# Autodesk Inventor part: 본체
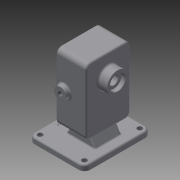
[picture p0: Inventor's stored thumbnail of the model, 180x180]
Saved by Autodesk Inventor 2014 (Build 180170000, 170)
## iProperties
Created: 2020-04
Part Number: 본체
Material: Generic
Document SubType Name: Modeling
Designer: kh
Density: 1 g/cm^3
Appearance: Default
Author: kh
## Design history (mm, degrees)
sketch "스케치1"
  geometry: L1 (-50, 60)-(50, 60); L2 (50, 60)-(50, -60); L3 (50, -60)-(-50, -60); L4 (-50, -60)-(-50, 60); L5 (-50, 60)-(50, -60); L6 (50, 60)-(-50, -60); 1 further point
  constraints: 12 end point, 2 midpoint, 2 parallel, 1 horizontal, 1 perpendicular
  dimensions: "d0" = 100 distance of L1.start L1.end; "d1" = 120 distance of L3.end L1.start
extrude "돌출1" new body sketch "스케치1" distance "d2" = 10; taper "d3" = 0 deg
fillet "모깎기1" dims "d7" = 10
sketch "스케치4"
  geometry: A1 r 10 centre (-40, 50) between (-40, 60) and (-50, 50) reference; A2 r 10 centre (40, 50) between (50, 50) and (40, 60) reference; A3 r 10 centre (40, -50) between (40, -60) and (50, -50) reference; A4 r 10 centre (-40, -50) between (-50, -50) and (-40, -60) reference; 1 further point
hole "구멍2" sketch "스케치4" at (-40, -50), (40, -50), (40, 50), (-40, 50) diameter "d17" = 9; stored, may be unused: countersink angle "d21" = 90 deg, drill point angle "d23" = 118 deg; dims "d18" = 6, "d19" = 4, "d20" = 2, "d22" = 8
fillet "모깎기2" dims "d24" = 3
sketch "스케치5"
  geometry: L1 (-33, 150)-(20, 150); L2 (20, 150)-(20, 30); L3 (20, 30)-(-33, 30); L4 (-33, 30)-(-33, 150); L5 (50, 0)-(40, 0) reference; L6 (50, 0)-(50, 7) reference; L7 (-50, 7)-(-50, 0) reference; 2 further points
  constraints: 8 end point, 2 parallel, 1 horizontal, 1 midpoint, 1 perpendicular, 1 vertical alignment
  dimensions: "d25" = 53 distance of L1.start L1.end; "d26" = 120 distance of L3.end L1.start; "d27" = 150 distance between parallel lines of L5 L1; "d114" = 70 distance between parallel lines of L7 L2
extrude "돌출2" join sketch "스케치5" stored distance "d28" = 80; taper "d29" = 0 deg
fillet "모깎기3" dims "d31" = 9
sketch "스케치8"
  geometry: A1 r 9 centre (9, 62) between (9, 71) and (0, 62) reference; A2 r 9 centre (111, 62) between (120, 62) and (111, 71) reference; A3 r 9 centre (111, 0) between (111, -9) and (120, 0) reference; A4 r 9 centre (9, 0) between (0, 0) and (9, -9) reference; 5 further points
  constraints: 4 horizontal alignment, 2 vertical alignment
  dimensions: "d32" = 29 distance of point (82, 62) A2.centre; "d33" = 44 distance of point (38, 62) point (82, 62)
hole "구멍3" sketch "스케치8" at (38, 62), (82, 62), (82, 0), (38, 0), (111, 62), (9, 62), (9, 0), (111, 0) diameter "d34" = 4.459; stored, may be unused: countersink angle "d38" = 90 deg, drill point angle "d40" = 118 deg; dims "d35" = 10, "d36" = 4, "d37" = 2, "d39" = 12
sketch "스케치10"
  geometry: L1 (60, 58.202)-(60, 12); L2 (150, 81)-(150, -19) reference; C1 r 19 at (38, 31); 1 further point
  constraints: 2 end point, 1 centre point, 1 horizontal alignment, 1 vertical
  dimensions: "d41" = 38 diameter of C1; "d56" = 90 distance between parallel lines of L1 L2; "d58" = 22 distance from line of C1.centre L1
extrude "돌출3" join sketch "스케치10" distance "d43" = 17; taper "d44" = 0 deg
sketch "스케치11"
  geometry: C1 r 19 at (0, 0) reference; C2 r 14 at (0, 0); 1 further point
  constraints: 1 centre point, 1 coincident
  dimensions: "d45" = 28 diameter of C2
extrude "돌출4" cut sketch "스케치11" distance "d46" = 7.3; taper "d47" = 0 deg
chamfer "모따기1" distance "d48" = 0.7; stored, may be unused: second distance "d49" = 2, angle "d50" = 30 deg
sketch "스케치14"
  geometry: L1 (38, 31)-(82, 31); L2 (38, 55)-(82, 55); L3 (82, 7)-(38, 7); L4 (49, 79)-(71, 79) reference; L5 (49, 74)-(71, 74) reference; L6 (71, -17)-(49, -17) reference; L7 (71, -12)-(49, -12) reference; L8 (-30, -19)-(-30, 81) reference; A1 r 24 centre (38, 31) between (38, 55) and (38, 7); A2 r 24 centre (82, 31) between (82, 7) and (82, 55); 5 further points
  constraints: 8 end point, 4 midpoint, 4 point on circle, 4 tangent, 2 centre point, 2 vertical alignment, 1 horizontal, 1 horizontal alignment, 1 parallel
  dimensions: "d66" = 24 radius of A2; "d67" = 44 distance of L2.start L2.end
extrude "돌출7" cut sketch "스케치14" distance "d68" = 29; taper "d69" = 0 deg
sketch "스케치15"
  geometry: L1 (38, 55)-(82, 55) reference; L2 (82, 7)-(38, 7) reference; C1 r 12.5 at (82, 31); C2 r 12.5 at (38, 31); A1 r 24 centre (38, 31) between (38, 55) and (38, 7) reference; A2 r 24 centre (82, 31) between (82, 7) and (82, 55) reference; 1 further point
  constraints: 2 centre point, 2 coincident
  dimensions: "d70" = 25 diameter of C1; "d71" = 25 diameter of C2
extrude "돌출8" cut sketch "스케치15" distance "d72" = 15; taper "d73" = 0 deg
sketch "스케치16"
  geometry: C1 r 12.5 at (0, 0) reference; C2 r 8.5 at (0, 0); 1 further point
  constraints: 1 centre point, 1 coincident
  dimensions: "d74" = 17 diameter of C2
extrude "돌출9" cut sketch "스케치16" stored distance "d75" = 15; taper "d76" = 0 deg
fillet "모깎기6" dims "d77" = 0.5
chamfer "모따기2" distance "d78" = 1; stored, may be unused: second distance "d79" = 2, angle "d80" = 30 deg
node "작업 평면4"
sketch "스케치19"
  geometry: L1 (-20, 141)-(-20, 39) reference; L2 (40, 0)-(-40, 0) reference; C1 r 11 at (-6, 90); 1 further point
  constraints: 1 centre point
  dimensions: "d92" = 22 diameter of C1; "d93" = 14 distance from line of C1.centre L1; "d94" = 90 distance from line of L2 C1.centre
extrude "돌출10" join sketch "스케치19" stored distance "d95" = 15; taper "d96" = 0 deg
fillet "모깎기7" dims "d97" = 3
hole "구멍5" diameter "d100" = 8.917; stored, may be unused: countersink angle "d104" = 90 deg, drill point angle "d106" = 118 deg; dims "d98" = 10, "d99" = 10, "d101" = 10, "d102" = 4, "d103" = 2, "d105" = 12
sketch "스케치22"
  geometry: L1 (-41.497, 20.739)-(-41.497, -20.739); L2 (-41.497, -20.739)-(-38.503, -20.739); L3 (-38.503, -20.739)-(-38.503, 20.739); L4 (-38.503, 20.739)-(-41.497, 20.739); L5 (-40, 20.739)-(-40, -20.739); L6 (-38.503, 0)-(-41.497, 0); L7 (40, 60)-(-40, 60) reference; L8 (-50, 50)-(-50, -50) reference; 1 further point
  constraints: 4 end point, 4 midpoint, 2 other
  dimensions: "d117" = 60 distance between parallel lines of L6 L7; "d118" = 10 distance between parallel lines of L5 L8
feature "엠보싱1" sketch "스케치22" dims "d0" = 100, "d1" = 120, "d119" = 0.5, "d120" = 0
sketch "스케치24"
  geometry: L1 (-20, 24)-(33, 24); L2 (33, 24)-(33, -24); L3 (33, -24)-(-20, -24); L4 (-20, -24)-(-20, 24); L5 (50, -50)-(50, 50) reference; 2 further points
  constraints: 8 end point, 2 parallel, 1 horizontal, 1 horizontal alignment, 1 midpoint, 1 perpendicular
  dimensions: "d125" = 17 distance between parallel lines of L2 L5; "d126" = 53 distance of L2.end L3.end; "d127" = 48 distance of L3.end L1.start
extrude "돌출12" join sketch "스케치24" stored distance "d128" = 15; taper "d129" = 0 deg
sketch "스케치25"
  geometry: L1 (53, 0)-(53, 20) reference; L2 (0, 0)-(53, 0) reference; L3 (0, 0)-(0, 20) reference; L4 (53, 20)-(0, 20) reference; L5 (11.547, 20)-(0, 0); L6 (41.453, 20)-(53, 0); L7 (11.547, 20)-(0, 20); L8 (0, 0)-(0, 20); L9 (41.453, 20)-(53, 20); L10 (53, 20)-(53, 0); 1 further point
  constraints: 12 end point, 4 collinear, 2 point on line
  dimensions: "d130" = 60 deg angle of L2 L5; "d131" = 60 deg angle of L2 L6
extrude "돌출13" cut sketch "스케치25" stored distance "d132" = 15; taper "d133" = 0 deg
fillet "모깎기10" dims "d134" = 3
fillet "모깎기11" dims "d135" = 3
node "솔리드1"
mirror "대칭1"
node "투영된 루프1"
node "투영된 루프4"
node "투영된 루프5"
other parameters: "d91" = -48
